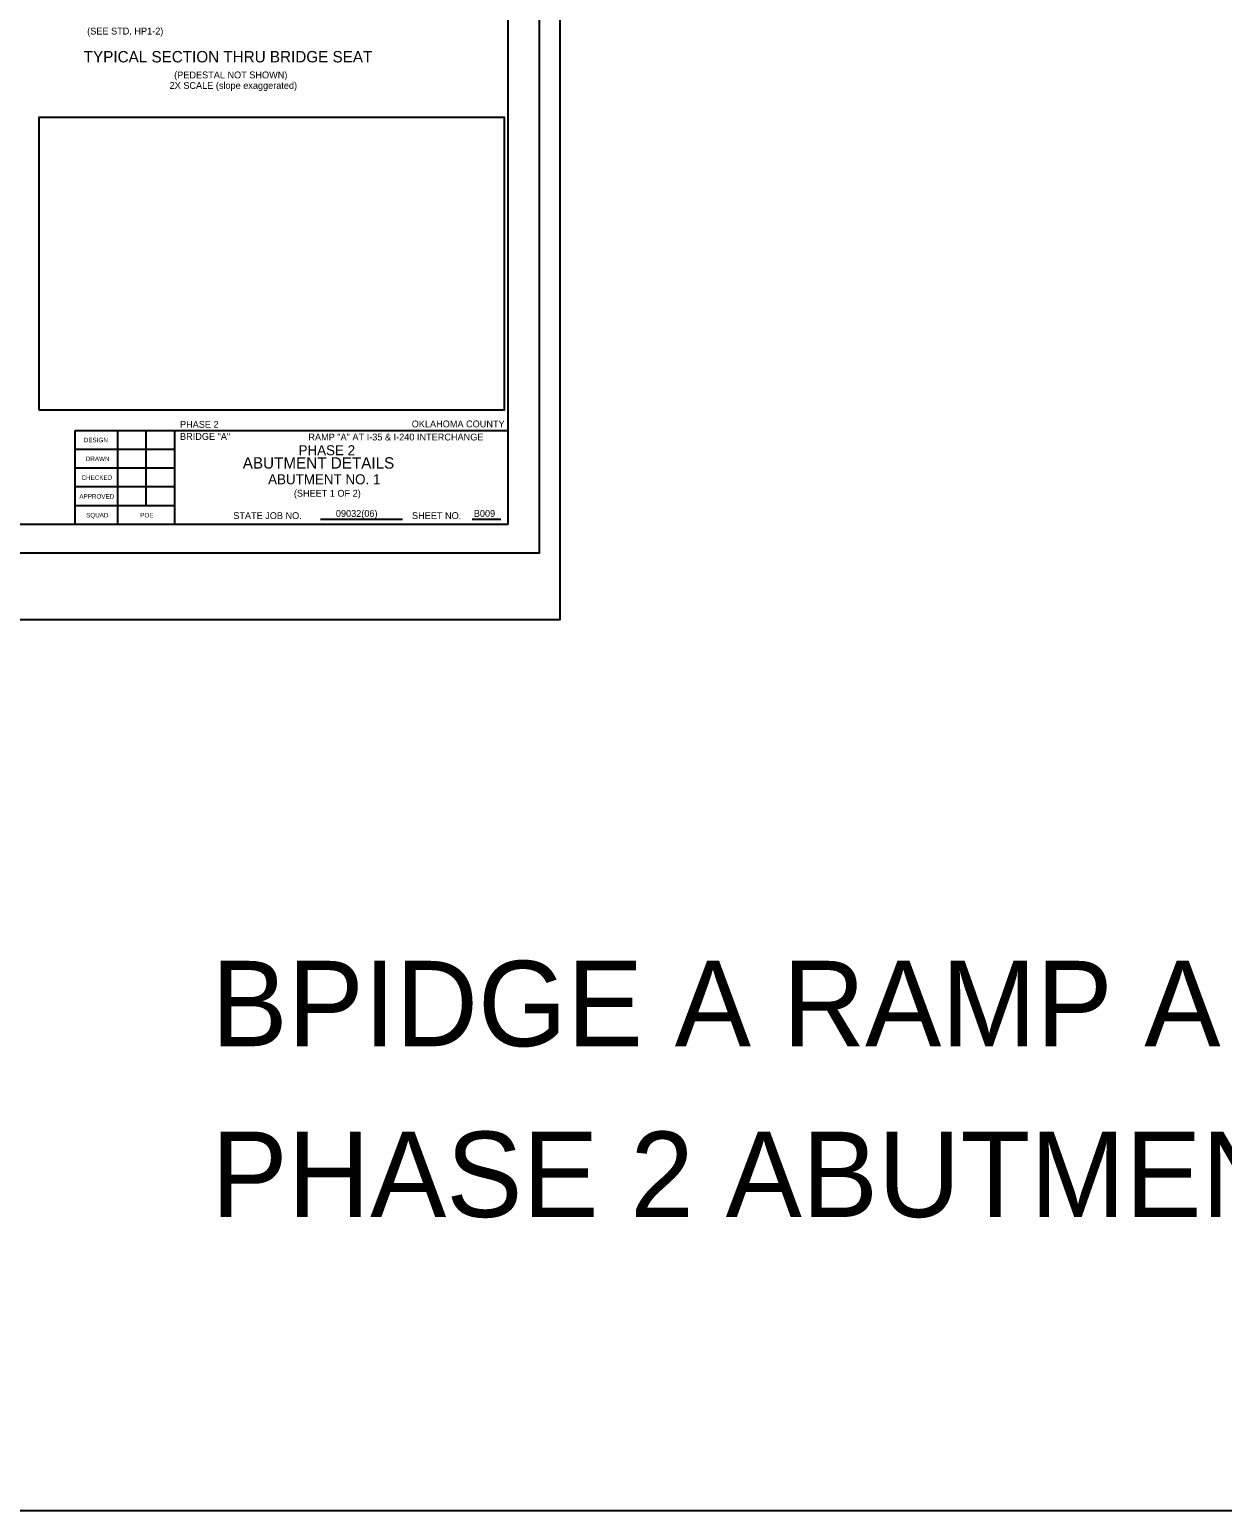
# Model space of a CAD drawing. Extents: x 2146833 to 2153191, y 139029 to 144029.
# Drawn here: x 2147031 to 2147114.8, y 143804.8 to 143908.8 of the extents above; entities that cross this region are included whole.
import ezdxf

# ---------------------------------------------------------------- set-up
doc = ezdxf.new("R2010")
doc.units = 0
for name, color, linetype in [('PR_Dimensions', 7, 'Continuous'), ('S', 7, 'Continuous'), ('SHT_Plot_Shape_Full', 7, 'Continuous'), ('SHT_Plot_Shape_Half', 7, 'Continuous'), ('SHT_Sheet_Border', 7, 'Continuous'), ('SHT_Standard_Sheet_Lines', 7, 'Continuous'), ('SHT_Standard_Sheet_Txt', 7, 'Continuous'), ('T', 7, 'Continuous'), ('T-Subtitle', 7, 'Continuous'), ('T-Title', 7, 'Continuous')]:
    doc.layers.add(name, color=color, linetype=linetype)

msp = doc.modelspace()

# ---------------------------------------------------------------- linework, layer by layer
at = {"layer": 'PR_Dimensions'}
msp.add_lwpolyline([(2147031.65, 143882.11), (2147064.37, 143882.11), (2147064.37, 143902.67), (2147031.65, 143902.67)], close=True, dxfattribs=at)
at = {"layer": 'S'}
msp.add_lwpolyline([(2146832.95, 143804.8), (2147328.38, 143804.8), (2147328.38, 144028.75), (2146832.95, 144028.75)], close=True, dxfattribs=at)
at = {"layer": 'SHT_Plot_Shape_Full'}
msp.add_lwpolyline([(2146924.25, 143963.36), (2147068.25, 143963.36), (2147068.25, 143867.36), (2146924.25, 143867.36)], close=True, dxfattribs=at)
at = {"layer": 'SHT_Plot_Shape_Half'}
msp.add_lwpolyline([(2146930.8, 143960.06), (2147066.8, 143960.06), (2147066.8, 143872.06), (2146930.8, 143872.06)], close=True, dxfattribs=at)
at = {"layer": 'SHT_Sheet_Border'}
for p, q in [((2147034.2, 143874.06), (2147034.2, 143880.66)), ((2147034.2, 143880.66), (2147064.6, 143880.66)), ((2147041.2, 143874.06), (2147041.2, 143880.67)), ((2147041.2, 143874.06), (2147041.2, 143880.67))]:
    msp.add_line(p, q, dxfattribs=at)
msp.add_lwpolyline([(2147064.6, 143874.06), (2146938.6, 143874.06), (2146938.6, 143958.06), (2147064.6, 143958.06)], close=True, dxfattribs=at)
at = {"layer": 'SHT_Standard_Sheet_Lines'}
for p, q in [((2147037.2, 143874.06), (2147037.2, 143880.67)), ((2147039.2, 143875.39), (2147039.2, 143880.67)), ((2147051.45, 143874.45), (2147057.21, 143874.45)), ((2147051.45, 143874.45), (2147057.21, 143874.45)), ((2147062.1, 143874.45), (2147064.11, 143874.45)), ((2147062.1, 143874.45), (2147064.11, 143874.45))]:
    msp.add_line(p, q, dxfattribs=at)
for points in [[(2147041.2, 143879.34), (2147034.2, 143879.34)], [(2147041.2, 143878.02), (2147034.2, 143878.02)], [(2147041.2, 143876.7), (2147034.2, 143876.7)], [(2147041.2, 143875.38), (2147034.2, 143875.38)]]:
    msp.add_lwpolyline(points, dxfattribs=at)

# ---------------------------------------------------------------- texts
at = {"layer": 'Defpoints'}
for s, height, p in [('2X SCALE (slope exaggerated)', 0.48, (2147040.84, 143904.67)), ('PHASE 2', 0.703, (2147049.9, 143878.93))]:
    msp.add_text(s, height=height, dxfattribs=at).set_placement(p)
at = {"layer": 'S'}
for s, p in [('BPIDGE A RAMP A', (2147043.78, 143837.41)), ('PHASE 2 ABUTMENT', (2147043.78, 143825.41))]:
    msp.add_text(s, height=6, dxfattribs=at).set_placement(p)
at = {"layer": 'SHT_Standard_Sheet_Txt'}
for s, height, p in [('DESIGN', 0.32, (2147034.81, 143879.84)), ('DRAWN', 0.32, (2147034.95, 143878.52)), ('CHECKED', 0.32, (2147034.65, 143877.2)), ('APPROVED', 0.32, (2147034.5, 143875.88)), ('SQUAD', 0.32, (2147034.97, 143874.56)), ('POE', 0.32, (2147038.78, 143874.56)), ('STATE JOB NO.', 0.48, (2147045.31, 143874.45)), ('STATE JOB NO.', 0.48, (2147045.31, 143874.45)), ('SHEET NO. ', 0.48, (2147057.87, 143874.45)), ('SHEET NO. ', 0.48, (2147057.87, 143874.45))]:
    msp.add_text(s, height=height, dxfattribs=at).set_placement(p)
at = {"layer": 'T'}
for s, height, p in [('(SEE STD. HP1-2)', 0.48, (2147035.05, 143908.49)), ('(PEDESTAL NOT SHOWN)', 0.48, (2147041.16, 143905.41)), ('PHASE 2', 0.48, (2147041.57, 143880.86)), ('OKLAHOMA COUNTY', 0.48, (2147057.85, 143880.89)), ('BRIDGE "A"', 0.48, (2147041.57, 143880.01)), ('RAMP "A" AT I-35 & I-240 INTERCHANGE', 0.48, (2147050.59, 143879.97)), ('(SHEET 1 OF 2)', 0.4792, (2147049.57, 143876.02)), ('09032(06)', 0.48, (2147052.52, 143874.6)), ('B009', 0.48, (2147062.21, 143874.6))]:
    msp.add_text(s, height=height, dxfattribs=at).set_placement(p)
at = {"layer": 'T-Subtitle'}
msp.add_text('ABUTMENT NO. 1', height=0.7031, dxfattribs=at).set_placement((2147047.76, 143876.89))
at = {"layer": 'T-Title'}
for s, p in [('TYPICAL SECTION THRU BRIDGE SEAT', (2147034.81, 143906.53)), ('ABUTMENT DETAILS', (2147045.98, 143877.99))]:
    msp.add_text(s, height=0.8, dxfattribs=at).set_placement(p)

doc.saveas('drawing.dxf')
